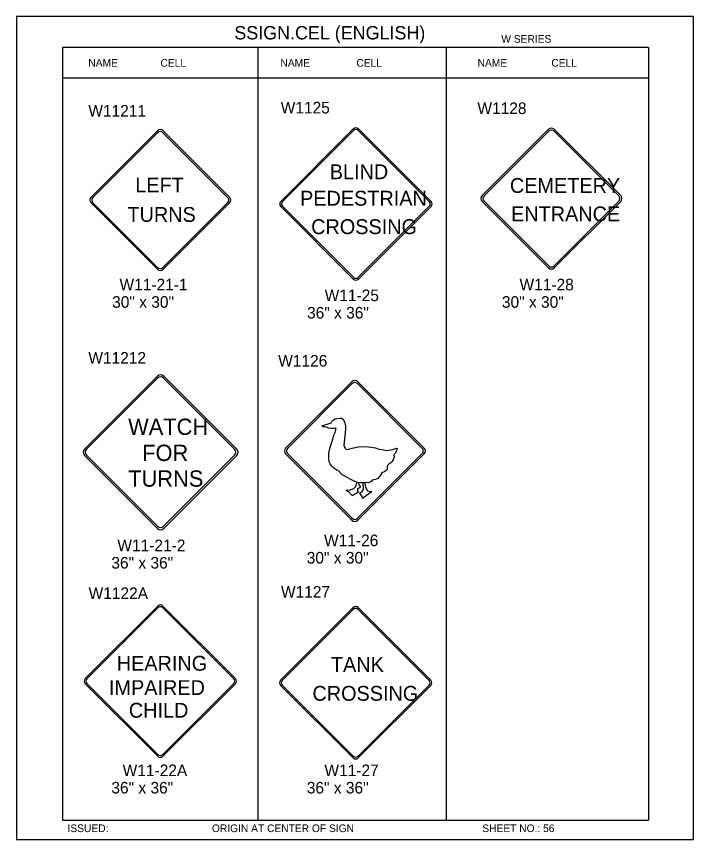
# Model space of a CAD drawing. Extents: x -5299 to 22597, y -19549 to -1808.
# Drawn here: x 945 to 1646, y -6387 to -5535 of the extents above; entities that cross this region are included whole.
import ezdxf

# ---------------------------------------------------------------- set-up
doc = ezdxf.new("R2010")
doc.units = 0
for name, color, linetype in [('Level 1', 7, 'Continuous'), ('Level 2', 7, 'Continuous'), ('Level 3', 7, 'Continuous'), ('Level 62', 7, 'Continuous')]:
    doc.layers.add(name, color=color, linetype=linetype)

msp = doc.modelspace()

# ---------------------------------------------------------------- linework, layer by layer
at = {"layer": 'Level 1'}
for p, q in [((1599.73, -5567.18), (992.71, -5567.18)), ((992.71, -5567.18), (992.71, -6367.18)), ((1195.05, -5567.18), (1195.05, -6367.18)), ((1390.18, -5567.18), (1390.18, -6367.18)), ((1599.73, -5567.18), (1599.73, -6367.18)), ((1599.73, -5598.85), (992.71, -5598.85)), ((1022.39, -5722.13), (1091.14, -5653.38)), ((1024.38, -5722.38), (1091.39, -5655.38)), ((1096.87, -5655.38), (1163.87, -5722.38)), ((1097.12, -5653.38), (1165.86, -5722.13)), ((1218.87, -5726.46), (1293.98, -5651.35)), ((1220.66, -5726.69), (1294.2, -5653.14)), ((1299.12, -5653.14), (1372.67, -5726.69)), ((1299.35, -5651.35), (1374.46, -5726.46)), ((1427.34, -5720.54), (1496.08, -5651.8)), ((1429.33, -5720.79), (1496.33, -5653.79)), ((1501.81, -5653.79), (1568.81, -5720.79)), ((1502.06, -5651.8), (1570.81, -5720.54)), ((1091.39, -5794.86), (1024.38, -5727.86)), ((1094.13, -5724.65), (1094.13, -5724.65)), ((1163.87, -5727.86), (1096.87, -5794.86)), ((1496.08, -5795.27), (1427.34, -5726.52)), ((1496.33, -5793.27), (1429.33, -5726.27)), ((1499.08, -5723.06), (1499.08, -5723.06)), ((1568.81, -5726.27), (1501.81, -5793.28)), ((1570.81, -5726.52), (1502.06, -5795.27)), ((1091.14, -5796.85), (1022.39, -5728.11)), ((1165.86, -5728.11), (1097.12, -5796.85)), ((1293.98, -5806.94), (1218.87, -5731.83)), ((1294.2, -5805.15), (1220.66, -5731.6)), ((1297.37, -5728.59), (1297.37, -5728.59)), ((1372.67, -5731.6), (1299.12, -5805.15)), ((1374.46, -5731.83), (1299.35, -5806.94)), ((1015.5, -5982.97), (1091.12, -5907.35)), ((1017.69, -5983.24), (1091.39, -5909.54)), ((1097.42, -5909.54), (1171.12, -5983.24)), ((1097.69, -5907.35), (1173.32, -5982.97)), ((1223.85, -5981.99), (1292.59, -5913.24)), ((1225.84, -5982.24), (1292.84, -5915.24)), ((1298.32, -5915.24), (1365.32, -5982.24)), ((1298.57, -5913.24), (1367.32, -5981.99)), ((1091.12, -6065.16), (1015.5, -5989.54)), ((1091.39, -6062.97), (1017.69, -5989.27)), ((1094.41, -5986.26), (1094.41, -5986.26)), ((1171.12, -5989.27), (1097.42, -6062.97)), ((1173.32, -5989.54), (1097.7, -6065.16)), ((1292.59, -6056.72), (1223.85, -5987.97)), ((1292.84, -6054.72), (1225.84, -5987.72)), ((1295.59, -5984.51), (1295.59, -5984.51)), ((1365.32, -5987.72), (1298.32, -6054.72)), ((1367.32, -5987.97), (1298.57, -6056.72)), ((1016.39, -6220.63), (1091.51, -6145.52)), ((1096.87, -6145.52), (1171.98, -6220.63)), ((1018.18, -6220.85), (1091.73, -6147.3)), ((1096.65, -6147.3), (1170.19, -6220.85)), ((1218.61, -6222.32), (1293.73, -6147.2)), ((1220.4, -6222.54), (1293.95, -6148.99)), ((1298.87, -6148.99), (1372.41, -6222.54)), ((1299.09, -6147.2), (1374.2, -6222.32)), ((1091.51, -6301.11), (1016.39, -6225.99)), ((1091.73, -6299.32), (1018.18, -6225.77)), ((1094.9, -6222.76), (1094.9, -6222.76)), ((1170.19, -6225.77), (1096.65, -6299.32)), ((1171.98, -6225.99), (1096.87, -6301.11)), ((1293.73, -6302.79), (1218.61, -6227.68)), ((1293.95, -6301.01), (1220.4, -6227.46)), ((1297.12, -6224.44), (1297.12, -6224.44)), ((1372.41, -6227.46), (1298.87, -6301)), ((1374.2, -6227.68), (1299.09, -6302.79)), ((992.71, -6367.18), (1599.73, -6367.18))]:
    msp.add_line(p, q, dxfattribs=at)
for points in [[(1261.74, -5959.52), (1262.51, -5958.57), (1263.51, -5958.19), (1266.89, -5957.32), (1271.14, -5955.69), (1271.77, -5954.44), (1273.14, -5952.94), (1274.89, -5951.81), (1277.52, -5951.19), (1280.02, -5950.94), (1281.65, -5951.06), (1283.53, -5952.19), (1284.28, -5953.31), (1285.28, -5956.19), (1285.78, -5958.94), (1286.03, -5961.69), (1285.53, -5966.32), (1284.15, -5978.95), (1284.78, -5981.08), (1285.4, -5982.2), (1285.74, -5982.89), (1287.53, -5983.33), (1289.15, -5982.95), (1294.16, -5981.58), (1299.16, -5980.7), (1303.16, -5980.33), (1309.41, -5980.58), (1312.92, -5981.08), (1316.79, -5981.83), (1320.42, -5983.21), (1325.55, -5983.83), (1328.43, -5984.45), (1334.43, -5983.58), (1339.18, -5982.08), (1339.56, -5982.08), (1338.68, -5984.83), (1338.06, -5986.21), (1337.44, -5987.73), (1336.18, -5988.58), (1335.6, -5989.13), (1336.43, -5990.84), (1336.31, -5991.84), (1335.18, -5994.21), (1333.81, -5996.34), (1332.68, -5997.34), (1330.93, -5998.71), (1329.3, -6000.09), (1329.18, -6001.47), (1329.18, -6002.84), (1328.93, -6004.09), (1327.92, -6005.09), (1326.42, -6006.47), (1324.3, -6007.22), (1323.55, -6007.72), (1321.55, -6011.1), (1319.42, -6013.6), (1317.05, -6014.35), (1313.42, -6015.1), (1312.42, -6016.85), (1312.04, -6016.97), (1311.17, -6017.35), (1309.29, -6017.85), (1307.66, -6017.6), (1305.16, -6018.1), (1302.54, -6018.1), (1299.91, -6017.85), (1297.41, -6017.35), (1294.91, -6016.1), (1291.53, -6014.6), (1287.65, -6012.6), (1285.15, -6011.1), (1282.52, -6009.72), (1278.27, -6005.34), (1276.77, -6004.84), (1275.02, -6003.59), (1273.39, -6002.34), (1271.77, -6000.59), (1269.98, -5998.2), (1269.02, -5996.34), (1268.51, -5992.48), (1268.77, -5989.08), (1269.14, -5985.33), (1269.64, -5982.33), (1271.02, -5978.08), (1272.14, -5974.95), (1273.02, -5971.2), (1273.89, -5968.45), (1275.27, -5965.82), (1276.15, -5961.69), (1273.39, -5961.57), (1270.64, -5961.57), (1268.77, -5961.44), (1267.27, -5960.57), (1265.89, -5960.19), (1264.02, -5959.94), (1262.01, -5959.82)], [(1297.41, -6017.48), (1296.16, -6022.23), (1294.91, -6023.48), (1292.53, -6024.86), (1290.28, -6025.6), (1286.15, -6025.86), (1289.03, -6026.86), (1292.78, -6031.23), (1298.78, -6027.73), (1299.28, -6027.61), (1298.66, -6026.61), (1298.78, -6023.85), (1301.41, -6022.48), (1301.41, -6021.85), (1299.91, -6019.98), (1299.41, -6018.73), (1299.41, -6017.75)], [(1303.79, -6018.1), (1304.16, -6024.6), (1303.54, -6026.36), (1302.54, -6027.48), (1300.41, -6029.11), (1302.54, -6031.36), (1303.41, -6033.99), (1311.04, -6028.23), (1313.04, -6027.23), (1311.29, -6027.23), (1309.16, -6026.73), (1306.79, -6022.85), (1306.14, -6017.9)]]:
    msp.add_lwpolyline(points, dxfattribs=at)
for centre, radius, start, end in [((1296.66, -5654.03), 3.79, 45, 135), ((1499.07, -5654.79), 4.23, 45, 135), ((1094.13, -5656.37), 4.23, 45, 135), ((1094.13, -5658.12), 3.87, 45, 135), ((1296.66, -5655.6), 3.48, 45, 135), ((1499.07, -5656.53), 3.87, 45, 135), ((1025.38, -5725.12), 4.23, 135, 225), ((1027.13, -5725.12), 3.87, 135, 225), ((1161.13, -5725.12), 3.87, 315, 45), ((1162.88, -5725.12), 4.23, 315, 45), ((1221.55, -5729.15), 3.79, 135, 225), ((1223.12, -5729.15), 3.48, 135, 225), ((1370.21, -5729.15), 3.48, 315, 45), ((1371.78, -5729.15), 3.79, 315, 45), ((1430.32, -5723.53), 4.23, 135, 225), ((1432.07, -5723.53), 3.87, 135, 225), ((1566.07, -5723.53), 3.87, 315, 45), ((1567.82, -5723.53), 4.23, 315, 45), ((1094.13, -5792.12), 3.87, 225, 315), ((1499.07, -5792.28), 4.23, 225, 315), ((1499.07, -5790.53), 3.87, 225, 315), ((1094.13, -5793.87), 4.23, 225, 315), ((1296.66, -5804.26), 3.79, 225, 315), ((1296.66, -5802.69), 3.48, 225, 315), ((1094.41, -5910.63), 4.65, 45, 135), ((1094.41, -5912.55), 4.26, 45, 135), ((1295.58, -5916.23), 4.23, 45, 135), ((1295.58, -5917.98), 3.87, 45, 135), ((1018.79, -5986.25), 4.65, 135, 225), ((1020.7, -5986.25), 4.26, 135, 225), ((1168.11, -5986.26), 4.26, 315, 45), ((1170.03, -5986.26), 4.65, 315, 45), ((1226.83, -5984.98), 4.23, 135, 225), ((1228.58, -5984.98), 3.87, 135, 225), ((1362.58, -5984.98), 3.87, 315, 45), ((1364.33, -5984.98), 4.23, 315, 45), ((1295.58, -6053.73), 4.23, 225, 315), ((1295.58, -6051.98), 3.87, 225, 315), ((1094.41, -6061.88), 4.65, 225, 315), ((1094.41, -6059.96), 4.26, 225, 315), ((1094.19, -6148.2), 3.79, 45, 135), ((1094.19, -6149.76), 3.48, 45, 135), ((1296.41, -6149.89), 3.79, 45, 135), ((1296.41, -6151.45), 3.48, 45, 135), ((1019.08, -6223.31), 3.79, 135, 225), ((1020.64, -6223.31), 3.48, 135, 225), ((1167.74, -6223.31), 3.48, 315, 45), ((1169.3, -6223.31), 3.79, 315, 45), ((1221.3, -6225), 3.79, 135, 225), ((1371.52, -6225), 3.79, 315, 45), ((1222.86, -6225), 3.48, 135, 225), ((1369.96, -6225), 3.48, 315, 45), ((1094.19, -6298.42), 3.79, 225, 315), ((1094.19, -6296.86), 3.48, 225, 315), ((1296.41, -6300.11), 3.79, 225, 315), ((1296.41, -6298.55), 3.48, 225, 315)]:
    msp.add_arc(centre, radius, start, end, dxfattribs=at)
at = {"layer": 'Level 62'}
msp.add_lwpolyline([(945.21, -6387.37), (1646.25, -6387.37), (1646.25, -5534.99), (945.21, -5534.99)], close=True, dxfattribs=at)

# ---------------------------------------------------------------- texts
at = {"layer": 'Level 1'}
for s, height, p in [('BLIND', 15.363, (1269.62, -5703.51)), ('LEFT', 15.363, (1068.22, -5717.25)), ('CEMETERY', 15.363, (1456.13, -5717.69)), ('PEDESTRIAN', 15.363, (1238.85, -5730.93)), ('TURNS', 15.363, (1060.1, -5747.72)), ('ENTRANCE', 15.363, (1457.28, -5747.15)), ('CROSSING', 15.363, (1250.32, -5760.38)), ('WATCH', 16.899, (1060.83, -5968.36)), ('FOR', 16.899, (1075.37, -5995.37)), ('TURNS', 16.899, (1060.89, -6021.96)), ('HEARING', 15.366, (1049.07, -6212.52)), ('TANK', 15.363, (1270.8, -6213.71)), ('IMPAIRED', 15.366, (1041.01, -6237.7)), ('CROSSING', 15.366, (1251.66, -6243.66)), ('CHILD', 15.366, (1061.56, -6261.19))]:
    msp.add_text(s, height=height, dxfattribs=at).set_placement(p)
at = {"layer": 'Level 2'}
for s, p in [('W1125', (1218.81, -5635.41)), ('W1128', (1422.46, -5636.06)), ('W11211', (1019.62, -5638.67)), ('W11212', (1019.62, -5894.51)), ('W1126', (1216.2, -5897.58)), ('W1122A', (1019.92, -6138.3)), ('W1127', (1219.1, -6136.81))]:
    msp.add_text(s, height=12, dxfattribs=at).set_placement(p)
at = {"layer": 'Level 3'}
for s, height, p in [('SSIGN.CEL (ENGLISH)', 13.8566, (1170.79, -5558.79)), ('W SERIES', 7.918, (1447.23, -5562.23)), ('NAME', 7.918, (1019.59, -5587.01)), ('CELL', 7.918, (1094.3, -5587.01)), ('NAME', 7.918, (1218.51, -5587.01)), ('CELL', 7.918, (1297.12, -5587.01)), ('NAME', 7.918, (1422.68, -5587.01)), ('CELL', 7.918, (1499, -5587.01)), ('W11-21-1', 12, (1051.89, -5818.66)), ('W11-28', 12, (1466.09, -5818.66)), ('W11-25', 12, (1264.32, -5829.81)), ('30" x 30"', 12, (1044.29, -5836.66)), ('30" x 30"', 12, (1447.85, -5836.66)), ('36" x 36"', 12, (1246.09, -5847.81)), ('W11-21-2', 12, (1049.68, -6088.77)), ('W11-26', 12, (1263.67, -6083.56)), ('30" x 30"', 12, (1245.76, -6101.56)), ('36" x 36"', 12, (1043.45, -6106.77)), ('W11-22A', 12, (1055.16, -6321.7)), ('W11-27', 12, (1264.04, -6321.7)), ('36" x 36"', 12, (1043.45, -6339.7)), ('36" x 36"', 12, (1245.8, -6339.7)), ('ISSUED:', 7.918, (998.08, -6379.67)), ('ORIGIN AT CENTER OF SIGN', 7.9181, (1147.61, -6379.67)), ('SHEET NO.: 56', 7.918, (1427.55, -6379.67))]:
    msp.add_text(s, height=height, dxfattribs=at).set_placement(p)

doc.saveas('drawing.dxf')
